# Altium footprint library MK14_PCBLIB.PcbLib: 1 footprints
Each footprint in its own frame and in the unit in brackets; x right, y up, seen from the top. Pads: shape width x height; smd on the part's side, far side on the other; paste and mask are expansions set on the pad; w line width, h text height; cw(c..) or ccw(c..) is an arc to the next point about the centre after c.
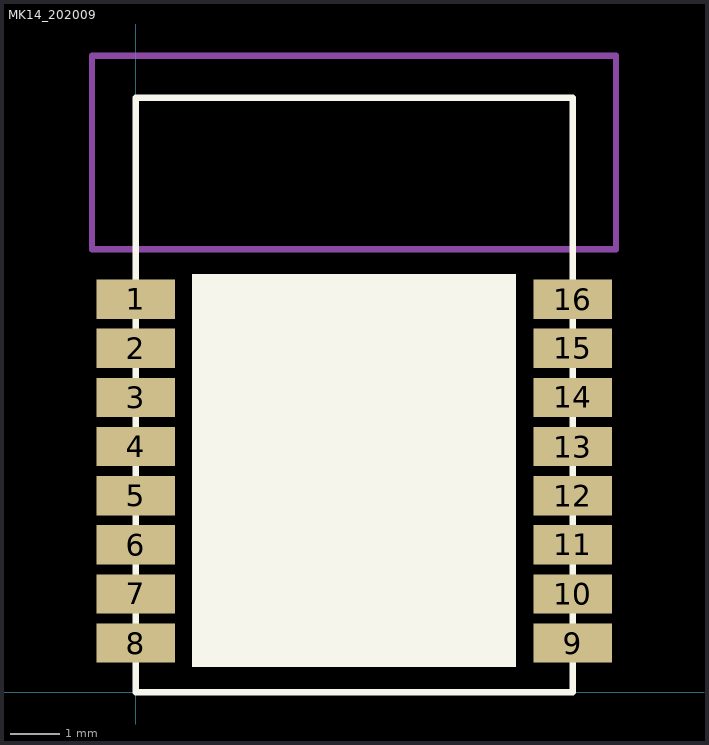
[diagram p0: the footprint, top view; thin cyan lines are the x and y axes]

## MK14_202009 [mm] "12.1*8.9mm"
height 2
pads (16):
  rect 1.6x0.8 smd: 1(0,8) 2(0,7) 3(0,6) 4(0,5) 5(0,4) 6(0,3) 7(0,2) 8(0,1) 9(8.9,1) 10(8.9,2) 11(8.9,3) 12(8.9,4) 13(8.9,5) 14(8.9,6) 15(8.9,7) 16(8.9,8)
Top Overlay:
  rectangle: 1.143,0.508 7.747,8.509
  lines w0.127: 0,0 8.9,0 8.9,12.1 0,12.1 0,0
Mechanical 2:
  lines w0.127: -0.889,9.017 -0.889,12.954 9.779,12.954 9.779,9.017 -0.889,9.017
  text "No ground pad" at 2.032,10.541 h0.38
